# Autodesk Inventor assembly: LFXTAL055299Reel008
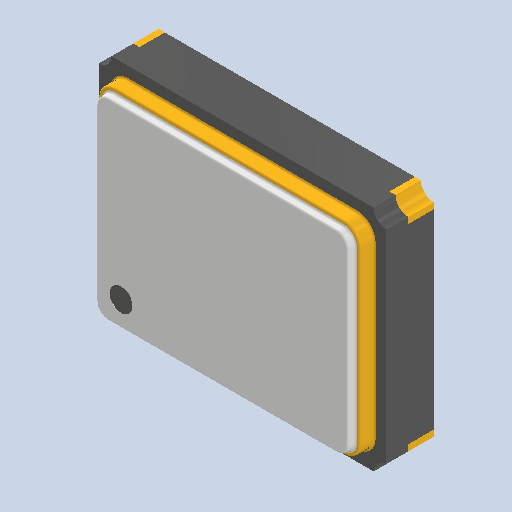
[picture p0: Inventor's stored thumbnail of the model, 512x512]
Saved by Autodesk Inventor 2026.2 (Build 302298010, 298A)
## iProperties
Created: 2026-10
Part Number: LFXTAL055299Reel008
Document SubType Name: Assembly
Designer: mel
Author: mel
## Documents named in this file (9)
- D:\travail\année 2026-2027\1 sti2d IT\poubelle à verre\raspberry-pico-2-microcontroller-rp2350-1.snapshot.5\raspberry_pico_2\raspberry_pico_2\LFXTAL055299Reel008.iam
- D:\travail\année 2026-2027\1 sti2d IT\poubelle à verre\raspberry-pico-2-microcontroller-rp2350-1.snapshot.5\raspberry_pico_2\raspberry_pico_2\LFXTAL055299Reel.ipt
- D:\travail\année 2026-2027\1 sti2d IT\poubelle à verre\raspberry-pico-2-microcontroller-rp2350-1.snapshot.5\raspberry_pico_2\raspberry_pico_2\LFXTAL055299Reel001.ipt
- D:\travail\année 2026-2027\1 sti2d IT\poubelle à verre\raspberry-pico-2-microcontroller-rp2350-1.snapshot.5\raspberry_pico_2\raspberry_pico_2\LFXTAL055299Reel002.ipt
- D:\travail\année 2026-2027\1 sti2d IT\poubelle à verre\raspberry-pico-2-microcontroller-rp2350-1.snapshot.5\raspberry_pico_2\raspberry_pico_2\LFXTAL055299Reel003.ipt
- D:\travail\année 2026-2027\1 sti2d IT\poubelle à verre\raspberry-pico-2-microcontroller-rp2350-1.snapshot.5\raspberry_pico_2\raspberry_pico_2\LFXTAL055299Reel004.ipt
- D:\travail\année 2026-2027\1 sti2d IT\poubelle à verre\raspberry-pico-2-microcontroller-rp2350-1.snapshot.5\raspberry_pico_2\raspberry_pico_2\LFXTAL055299Reel005.ipt
- D:\travail\année 2026-2027\1 sti2d IT\poubelle à verre\raspberry-pico-2-microcontroller-rp2350-1.snapshot.5\raspberry_pico_2\raspberry_pico_2\LFXTAL055299Reel006.ipt
- D:\travail\année 2026-2027\1 sti2d IT\poubelle à verre\raspberry-pico-2-microcontroller-rp2350-1.snapshot.5\raspberry_pico_2\raspberry_pico_2\LFXTAL055299Reel007.ipt
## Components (8 placed, 8 different names)
1. 2642
2. 2643
3. 2644
4. 2645
5. 2646
6. 2647
7. 2648
8. 2649
